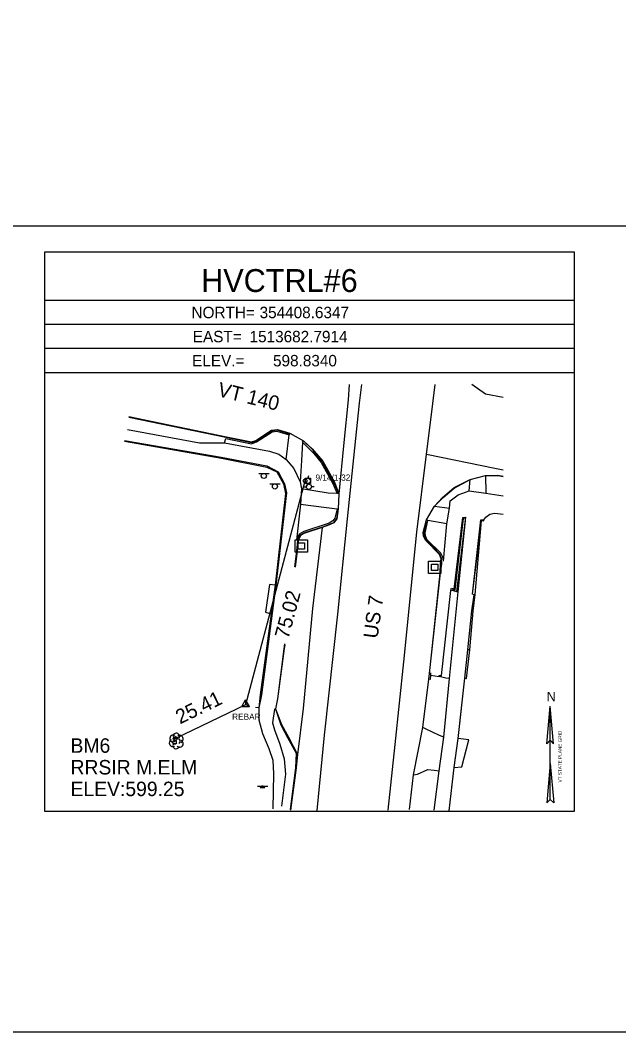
# Model space of a CAD drawing. Extents: x 1514039 to 1514679, y 870735 to 871155.
# Drawn here: x 1514308.6 to 1514432.7, y 870735.2 to 870945.2 of the extents above; entities that cross this region are included whole.
import ezdxf

# ---------------------------------------------------------------- set-up
doc = ezdxf.new("R2010")
doc.units = 0
for name, color, linetype in [('C_A', 7, 'Continuous'), ('CBP', 7, 'Continuous'), ('CPBM', 7, 'Continuous'), ('CPSM', 7, 'Continuous'), ('Default', 7, 'Continuous'), ('DS', 7, 'Continuous'), ('LBF', 7, 'Continuous'), ('LSOGP', 7, 'Continuous'), ('LTD', 7, 'Continuous'), ('LW', 7, 'Continuous'), ('LWS', 7, 'Continuous'), ('NBL1', 7, 'Continuous'), ('NBL2', 7, 'Continuous'), ('NNA_P', 7, 'Continuous'), ('PET', 7, 'Continuous'), ('PSP', 7, 'Continuous'), ('RC', 7, 'Continuous'), ('RDG', 7, 'Continuous'), ('RDP', 7, 'Continuous'), ('RSW', 7, 'Continuous'), ('SSGN', 7, 'Continuous'), ('U_C', 7, 'Continuous'), ('UP', 7, 'Continuous')]:
    doc.layers.add(name, color=color, linetype=linetype)

msp = doc.modelspace()

# ---------------------------------------------------------------- linework, layer by layer
at = {"layer": 'CBP'}
for centre, radius in [((1514367.69, 870849.59), 0.4), ((1514367.69, 870849.59), 0.0533), ((1514340.71, 870796.08), 0.4), ((1514340.71, 870796.08), 0.0533)]:
    msp.add_circle(centre, radius, dxfattribs=at)
at = {"layer": 'CPBM'}
for p, q in [((1514340.31, 870794.99), (1514340.31, 870795.63)), ((1514340.31, 870795.63), (1514340.95, 870795.63)), ((1514340.95, 870794.99), (1514340.31, 870794.99)), ((1514340.63, 870795.31), (1514340.63, 870795.31)), ((1514340.63, 870795.31), (1514340.63, 870795.31)), ((1514340.95, 870795.63), (1514340.95, 870794.99))]:
    msp.add_line(p, q, dxfattribs=at)
at = {"layer": 'CPSM'}
for p, q in [((1514354.53, 870802.73), (1514355.33, 870804.12)), ((1514354.53, 870802.73), (1514355.34, 870803.19)), ((1514356.13, 870802.73), (1514355.33, 870804.12)), ((1514355.34, 870803.19), (1514355.33, 870804.12)), ((1514355.34, 870803.19), (1514355.34, 870803.19)), ((1514355.34, 870803.19), (1514356.13, 870802.73)), ((1514354.53, 870802.73), (1514356.13, 870802.73))]:
    msp.add_line(p, q, dxfattribs=at)
at = {"layer": 'Default'}
for p, q in [((1514355.34, 870803.19), (1514367.71, 870849.59)), ((1514340.71, 870796.08), (1514355.34, 870803.19))]:
    msp.add_line(p, q, dxfattribs=at)
at = {"layer": 'DS'}
for p, q in [((1514365.61, 870837.34), (1514368.17, 870837.34)), ((1514365.61, 870834.78), (1514365.61, 870837.34)), ((1514366.25, 870835.42), (1514366.25, 870836.7)), ((1514366.25, 870836.7), (1514367.53, 870836.7)), ((1514367.53, 870836.7), (1514367.53, 870835.42)), ((1514368.17, 870837.34), (1514368.17, 870834.78)), ((1514368.17, 870834.78), (1514365.61, 870834.78)), ((1514367.53, 870835.42), (1514366.25, 870835.42)), ((1514366.9, 870836.07), (1514366.9, 870836.07)), ((1514366.9, 870836.07), (1514366.9, 870836.07)), ((1514393.27, 870832.92), (1514395.83, 870832.92)), ((1514393.27, 870830.36), (1514393.27, 870832.92)), ((1514393.91, 870831), (1514393.91, 870832.28)), ((1514393.91, 870832.28), (1514395.19, 870832.28)), ((1514395.19, 870832.28), (1514395.19, 870831)), ((1514395.83, 870832.92), (1514395.83, 870830.36)), ((1514395.83, 870830.36), (1514393.27, 870830.36)), ((1514395.19, 870831), (1514393.91, 870831)), ((1514394.55, 870831.64), (1514394.55, 870831.64)), ((1514394.55, 870831.64), (1514394.55, 870831.64))]:
    msp.add_line(p, q, dxfattribs=at)
at = {"layer": 'LBF'}
for points in [[(1514399.39, 870826.57), (1514399.12, 870826.58)], [(1514402.98, 870826), (1514402.74, 870825.95)], [(1514402.24, 870822.58), (1514402.56, 870822.56)], [(1514401.83, 870814.52), (1514401.41, 870814.53)], [(1514397.65, 870808.54), (1514396.84, 870808.62), (1514395.45, 870808.97)], [(1514400.83, 870808.62), (1514401.17, 870808.53)]]:
    msp.add_lwpolyline(points, dxfattribs=at)
at = {"layer": 'LSOGP'}
msp.add_lwpolyline([(1514398.11, 870785.92), (1514398.58, 870790.1), (1514400.15, 870790.19), (1514401.62, 870795.81), (1514399.41, 870796.13), (1514400.12, 870802.38), (1514400.83, 870808.62), (1514401.17, 870808.53), (1514401.83, 870814.52), (1514402.56, 870822.56), (1514402.98, 870826), (1514404.27, 870841.36), (1514404.76, 870841.3), (1514404.76, 870841.48), (1514405.14, 870842.07), (1514406.01, 870842.7), (1514406.97, 870842.85), (1514408.75, 870842.7)], dxfattribs=at)
at = {"layer": 'LTD'}
msp.add_line((1514340.92, 870795.63), (1514340.92, 870795.63), dxfattribs=at)
msp.add_line((1514340.92, 870795.63), (1514340.92, 870795.63), dxfattribs=at)
msp.add_arc((1514340.95, 870796.55), 0.67, 335.5272, 180.9563, dxfattribs=at)
for centre, major_axis, ratio, start_param, end_param in [((1514340.42, 870796.06), (0.775, -0.328), 0.895232, 1.570796, 4.712389), ((1514341.59, 870796), (-0.73, -0.309), 0.949671, 1.570796, 4.712389), ((1514340.23, 870795.18), (0.373, -0.667), 0.959034, 3.141593, 6.283185), ((1514340.92, 870794.67), (0.17, 0.679), 0.942809, 1.570796, 4.712389), ((1514340.63, 870795.15), (-0.4, -0.053), 0.423636, 0, 3.141593), ((1514340.79, 870795.92), (-0.133, -0.507), 0.645439, 3.141593, 6.283185), ((1514341.24, 870795.52), (-0.32, 0.427), 0.989748, 3.141593, 6.283185), ((1514341.56, 870795.1), (-0.697, 0.507), 0.841452, 1.570796, 4.712389)]:
    msp.add_ellipse(centre, major_axis=major_axis, ratio=ratio, start_param=start_param, end_param=end_param, dxfattribs=at)
at = {"layer": 'LW'}
for points in [[(1514399.12, 870826.58), (1514398.18, 870826.8), (1514398.25, 870826.98), (1514398.83, 870826.94), (1514400.54, 870841.81), (1514400.99, 870842.05)], [(1514399.12, 870826.58), (1514400.99, 870842.05)], [(1514402.42, 870826.06), (1514404.27, 870841.36), (1514404.76, 870841.3)]]:
    msp.add_lwpolyline(points, dxfattribs=at)
at = {"layer": 'LWS'}
msp.add_lwpolyline([(1514330.18, 870857.82), (1514350.3, 870854.29), (1514359.72, 870852.45), (1514361.79, 870851.44), (1514363.16, 870848.97), (1514363.63, 870846.95), (1514361.44, 870827.96), (1514360.64, 870821.97), (1514358.38, 870805.14), (1514358.08, 870802.45), (1514357.37, 870802.54)], dxfattribs=at)
at = {"layer": 'NBL1'}
msp.add_lwpolyline([(1514038.57, 870735.22), (1514678.57, 870735.22), (1514678.57, 871155.22), (1514038.57, 871155.22)], close=True, dxfattribs=at)
at = {"layer": 'NBL2'}
for p, q in [((1514038.57, 870902.55), (1514678.57, 870902.55)), ((1514423.57, 870887.05), (1514313.57, 870887.05)), ((1514423.57, 870882.05), (1514313.57, 870882.05)), ((1514423.57, 870877.05), (1514313.57, 870877.05)), ((1514423.57, 870872.05), (1514313.57, 870872.05))]:
    msp.add_line(p, q, dxfattribs=at)
msp.add_lwpolyline([(1514313.57, 870781.05), (1514423.57, 870781.05), (1514423.57, 870897.05), (1514313.57, 870897.05)], close=True, dxfattribs=at)
at = {"layer": 'NNA_P'}
for p, q in [((1514417.84, 870795), (1514418.54, 870802.79)), ((1514418.54, 870783.42), (1514418.54, 870802.79)), ((1514419.23, 870795), (1514418.54, 870802.79)), ((1514417.84, 870795), (1514418.54, 870795.77)), ((1514419.23, 870795), (1514418.54, 870795.77)), ((1514418.54, 870790.94), (1514417.82, 870782.78)), ((1514418.54, 870790.94), (1514419.26, 870782.78)), ((1514418.54, 870783.42), (1514417.82, 870782.78)), ((1514418.54, 870783.42), (1514419.26, 870782.78))]:
    msp.add_line(p, q, dxfattribs=at)
at = {"layer": 'PET'}
for points in [[(1514379.36, 870869.61), (1514378.91, 870865.69), (1514376.37, 870841.71), (1514374.41, 870821.9), (1514371.65, 870796.79), (1514370.12, 870781.16)], [(1514384.9, 870781.2), (1514386.35, 870794.87), (1514388.17, 870812.04), (1514390.84, 870838.97), (1514392.85, 870855.12), (1514393.71, 870861.7), (1514394.66, 870869.61)], [(1514408.75, 870866.91), (1514405.12, 870867.58), (1514402.26, 870869.61)], [(1514331.08, 870862.95), (1514351.34, 870858.71), (1514356.55, 870857.66), (1514357.48, 870857.97), (1514360.71, 870860.09), (1514361.94, 870860.25), (1514364.47, 870859.48), (1514367.33, 870857.87), (1514369.16, 870856.22), (1514369.55, 870855.78), (1514371.35, 870853.65), (1514373.75, 870849.31), (1514374.66, 870846.88)], [(1514392.85, 870855.12), (1514407.01, 870852.24), (1514408.75, 870851.9)]]:
    msp.add_lwpolyline(points, dxfattribs=at)
at = {"layer": 'PSP'}
for points in [[(1514376.79, 870869.61), (1514376.59, 870866.4), (1514375.69, 870857.57), (1514374.66, 870846.88), (1514374.53, 870843.75), (1514374.25, 870841.7), (1514373.65, 870840.87), (1514372.73, 870840.43), (1514371.24, 870839.91), (1514369.18, 870823.06), (1514367.25, 870802.31), (1514366.07, 870792.77), (1514365.79, 870790.01), (1514364.67, 870781.2)], [(1514389.3, 870781.35), (1514390.17, 870788.58), (1514392.12, 870798.38), (1514393.36, 870808.39), (1514393.48, 870809.52), (1514395.7, 870830.46), (1514395.76, 870832.43), (1514395.89, 870833.41), (1514395.52, 870834.29), (1514392.69, 870837.18), (1514392.24, 870838.08), (1514392.16, 870838.85), (1514392.84, 870841.5), (1514394.5, 870844.32), (1514396.14, 870846.13), (1514398.57, 870848.19), (1514401.88, 870849.86), (1514405.1, 870850.7), (1514407.65, 870850.77), (1514408.75, 870850.59)]]:
    msp.add_lwpolyline(points, dxfattribs=at)
at = {"layer": 'RC'}
for points in [[(1514331.1, 870862.81), (1514351.21, 870858.68), (1514356.57, 870857.56), (1514357.44, 870857.85), (1514360.71, 870860.01), (1514361.89, 870860.19), (1514364.42, 870859.38), (1514364.34, 870859.14)], [(1514367.11, 870857.65), (1514367.33, 870857.87), (1514369.14, 870856.18), (1514369.51, 870855.65), (1514371.21, 870853.55), (1514373.62, 870849.28), (1514374.66, 870846.88), (1514374.35, 870846.94)], [(1514394.5, 870844.32), (1514396.31, 870846.14), (1514398.61, 870848.08), (1514401.88, 870849.86)], [(1514405.1, 870850.7), (1514407.73, 870850.67), (1514408.75, 870850.52)], [(1514374.31, 870843.79), (1514374.53, 870843.75), (1514374.17, 870841.75), (1514373.56, 870840.91), (1514372.72, 870840.52), (1514371.27, 870839.99), (1514367.55, 870838.82), (1514366.62, 870838.35), (1514366.11, 870837.24), (1514365.89, 870835.02), (1514365.46, 870831.71)], [(1514393.71, 870809.71), (1514393.66, 870809.22), (1514393.61, 870808.37), (1514393.36, 870808.39), (1514393.5, 870809.58), (1514395.76, 870830.5), (1514396.04, 870832.39), (1514395.98, 870833.44), (1514395.64, 870834.36), (1514392.82, 870837.28), (1514392.48, 870838.12), (1514392.34, 870838.81), (1514392.84, 870841.5)], [(1514363.4, 870815.77), (1514363.27, 870814.75), (1514361.92, 870804.32), (1514361.55, 870802.27), (1514361.29, 870802.22)], [(1514361.55, 870802.27), (1514362.6, 870798.96), (1514364, 870796.34), (1514365.8, 870793.05), (1514365.67, 870790.04), (1514364.54, 870781.33)]]:
    msp.add_lwpolyline(points, dxfattribs=at)
at = {"layer": 'RDG'}
for points in [[(1514401.62, 870795.81), (1514399.41, 870796.13)], [(1514398.58, 870790.1), (1514400.15, 870790.19)]]:
    msp.add_lwpolyline(points, dxfattribs=at)
at = {"layer": 'RDP'}
for points in [[(1514371.24, 870839.91), (1514367.38, 870838.66), (1514366.72, 870838.24), (1514366.26, 870837.24), (1514366.05, 870835.03), (1514365.6, 870831.64)], [(1514363.44, 870815.52), (1514363.33, 870814.76), (1514361.92, 870804.32)], [(1514361.55, 870802.27), (1514362.75, 870798.99), (1514364.25, 870796.36), (1514366.07, 870792.77)], [(1514396.47, 870796.41), (1514395.53, 870796.75), (1514392.66, 870798.1), (1514392.12, 870798.38)], [(1514390.17, 870788.58), (1514391.01, 870788.69), (1514393.14, 870789.67), (1514394.43, 870789.52), (1514395.47, 870789.39)]]:
    msp.add_lwpolyline(points, dxfattribs=at)
at = {"layer": 'RSW'}
for points in [[(1514330.82, 870860.28), (1514345.75, 870857.47), (1514350.93, 870857.52)], [(1514350.93, 870857.52), (1514351.19, 870858.41), (1514356.55, 870857.3), (1514357.6, 870857.69), (1514360.84, 870859.78), (1514361.77, 870859.93), (1514364.34, 870859.14)], [(1514330.19, 870857.96), (1514350.26, 870854.5)], [(1514350.93, 870857.52), (1514360.3, 870855.77), (1514362.24, 870855.14), (1514363.73, 870854.02), (1514365.35, 870852.15), (1514366.66, 870849.38), (1514366.9, 870847.93), (1514366.7, 870844.78), (1514365.91, 870837.31)], [(1514363.73, 870854.02), (1514364.34, 870859.14)], [(1514367.11, 870857.65), (1514366.89, 870853.79), (1514366.66, 870849.38)], [(1514367.11, 870857.65), (1514369.46, 870855.27), (1514371, 870853.37), (1514373.36, 870849.16), (1514374.35, 870846.94), (1514372.43, 870847.07), (1514366.9, 870847.93)], [(1514350.26, 870854.5), (1514359.75, 870852.71), (1514362.05, 870851.46), (1514363.4, 870848.99), (1514363.82, 870847.08), (1514361.6, 870827.93), (1514360.84, 870822.12), (1514358.59, 870805.17), (1514358.08, 870802.45), (1514358.1, 870799.99), (1514358.83, 870797.15), (1514360.13, 870794.03), (1514360.94, 870791.58), (1514361.12, 870788.79), (1514360.95, 870781.53)], [(1514401.73, 870847.55), (1514401.88, 870849.86)], [(1514405.1, 870850.7), (1514405.17, 870847.05)], [(1514396.37, 870832.93), (1514397.1, 870840.64), (1514397.62, 870843.95), (1514397.74, 870845.44), (1514399.39, 870846.7), (1514401.73, 870847.55), (1514405.17, 870847.05), (1514408.75, 870846.48)], [(1514366.7, 870844.78), (1514372.1, 870844.06), (1514374.31, 870843.79), (1514373.82, 870841.85), (1514373.4, 870841.27), (1514372.64, 870840.78), (1514367.41, 870839.07), (1514366.45, 870838.5), (1514365.91, 870837.31)], [(1514394.5, 870844.32), (1514397.62, 870843.95)], [(1514397.56, 870781.07), (1514398.58, 870790.1), (1514399.41, 870796.13), (1514400.83, 870808.62), (1514401.41, 870814.53), (1514402.24, 870822.58), (1514402.74, 870825.95), (1514402.42, 870826.06), (1514404.14, 870841.51), (1514404.76, 870841.48), (1514405.14, 870842.07), (1514406.01, 870842.7), (1514406.97, 870842.85), (1514408.75, 870842.7)], [(1514396.37, 870832.93), (1514396.22, 870833.78), (1514395.82, 870834.59), (1514392.95, 870837.39), (1514392.66, 870838.16), (1514392.56, 870838.79), (1514393.15, 870841.34)], [(1514397.1, 870840.64), (1514393.15, 870841.34), (1514392.84, 870841.5)], [(1514393.66, 870809.22), (1514395.45, 870808.97), (1514395.49, 870809.21), (1514395.98, 870809.19), (1514397.93, 870826.84), (1514398.05, 870827.31), (1514398.62, 870827.14), (1514400.42, 870842.01), (1514400.99, 870842.05)], [(1514394.41, 870781.21), (1514395.47, 870789.39), (1514396.47, 870796.41), (1514397.65, 870808.54), (1514399.39, 870826.57), (1514400.99, 870842.05)], [(1514361.44, 870827.96), (1514360.25, 870828.09), (1514359.42, 870822.35), (1514360.64, 870821.97)], [(1514361.29, 870802.22), (1514360.9, 870799.37), (1514361.3, 870797.88), (1514362.4, 870794.96), (1514363.35, 870791.85), (1514363.57, 870788.67), (1514362.78, 870782.06)]]:
    msp.add_lwpolyline(points, dxfattribs=at)
at = {"layer": 'SSGN'}
for p, q in [((1514358.06, 870851.14), (1514360.19, 870851.14)), ((1514359.11, 870850.61), (1514359.11, 870850.61)), ((1514360.35, 870848.97), (1514362.49, 870848.97)), ((1514361.41, 870848.43), (1514361.41, 870848.43)), ((1514357.8, 870786.23), (1514359.93, 870786.23)), ((1514358.37, 870785.92), (1514359.34, 870785.92))]:
    msp.add_line(p, q, dxfattribs=at)
for centre in [(1514359.11, 870850.61), (1514361.41, 870848.43)]:
    msp.add_circle(centre, 0.533, dxfattribs=at)
msp.add_arc((1514358.85, 870785.7), 0.533, 24.9504, 155.0496, dxfattribs=at)
at = {"layer": 'UP'}
for p, q in [((1514367.71, 870849.05), (1514367.71, 870850.12)), ((1514367.71, 870850.12), (1514368.77, 870850.12)), ((1514368.77, 870849.05), (1514367.71, 870849.05)), ((1514368.08, 870848.52), (1514368.24, 870849.05)), ((1514368.4, 870850.65), (1514368.24, 870850.12)), ((1514368.24, 870849.59), (1514368.24, 870849.59)), ((1514368.77, 870850.12), (1514368.77, 870849.05)), ((1514367.41, 870848.36), (1514367.94, 870848.36)), ((1514368.47, 870848.36), (1514368.47, 870848.36)), ((1514369.54, 870848.36), (1514369.01, 870848.36)), ((1514369.01, 870848.36), (1514369.01, 870848.36)), ((1514369.54, 870848.36), (1514369.54, 870848.36))]:
    msp.add_line(p, q, dxfattribs=at)
for centre in [(1514368.24, 870849.59), (1514368.47, 870848.36)]:
    msp.add_circle(centre, 0.533, dxfattribs=at)

# ---------------------------------------------------------------- texts
at = {"layer": 'C_A'}
msp.add_text('REBAR', height=1.28, dxfattribs=at).set_placement((1514352.53, 870799.99))
at = {"layer": 'Default'}
for s, rotation, p in [('VT 140', 346.088, (1514349.33, 870867.23)), ('75.02', 75.0697, (1514364.2, 870816.64)), ('US 7', 82.1562, (1514382.7, 870816.74)), ('25.41', 25.9346, (1514341.71, 870799.02)), ('BM6', 360, (1514319, 870793.14)), ('RRSIR M.ELM', 360, (1514319, 870788.64)), ('ELEV:599.25', 360, (1514319, 870784.14))]:
    msp.add_text(s, height=3, rotation=rotation, dxfattribs=at).set_placement(p)
at = {"layer": 'NBL2'}
for s, height, p in [('HVCTRL#6', 4.75, (1514346.1, 870888.8)), ('NORTH=', 2.375, (1514344.1, 870883.36)), ('354408.6347', 2.375, (1514358.23, 870883.36)), ('EAST=', 2.375, (1514344.37, 870878.36)), ('1513682.7914', 2.375, (1514356.15, 870878.36)), ('ELEV.=', 2.375, (1514344.23, 870873.36)), ('   598.8340', 2.375, (1514358.37, 870873.36))]:
    msp.add_text(s, height=height, dxfattribs=at).set_placement(p)
at = {"layer": 'NNA_P'}
msp.add_text('N', height=1.97, dxfattribs=at).set_placement((1514417.78, 870803.81))
msp.add_text('VT STATE PLANE GRID', height=0.7, rotation=90.0204, dxfattribs=at).set_placement((1514420.89, 870786.98))
at = {"layer": 'U_C'}
msp.add_text('9/14/1-32', height=1.28, dxfattribs=at).set_placement((1514369.82, 870849.63))

doc.saveas('drawing.dxf')
